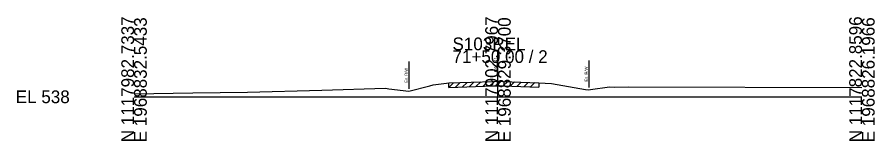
# Model space of a CAD drawing. Extents: x -26 to 163, y -10 to 24518.
# Drawn here: x -25.7 to 162.8, y 19990.3 to 20017.5 of the extents above; entities that cross this region are included whole.
import ezdxf

# ---------------------------------------------------------------- set-up
doc = ezdxf.new("R2010")
doc.units = 0
for name, color, linetype in [('RD_GPK_XS_Cell', 7, 'Continuous'), ('RD_XS_ExGround', 7, 'Continuous'), ('RD_XS_ExPaveRet', 7, 'Continuous'), ('RD_XS_ExRW', 7, 'Continuous'), ('RD_XS_TX_Elev_EX', 7, 'Continuous')]:
    doc.layers.add(name, color=color, linetype=linetype)

msp = doc.modelspace()

# ---------------------------------------------------------------- linework, layer by layer
at = {"layer": 'RD_GPK_XS_Cell'}
for p, q in [((80, 20000), (80, 20010.24)), ((0, 20000), (80, 20000)), ((80, 20000), (160, 20000))]:
    msp.add_line(p, q, dxfattribs=at)
at = {"layer": 'RD_XS_ExGround'}
msp.add_lwpolyline([(0, 20000.67), (12.96, 20000.89), (24.91, 20001.02), (41.3, 20001.48), (55.24, 20001.88), (56.02, 20001.77), (60.41, 20001.23), (65, 20002.41), (65.75, 20002.6), (68.67, 20002.98), (69.16, 20003.04), (79.02, 20003.38), (80.14, 20003.41), (81.04, 20003.38), (89.01, 20003.09), (91.77, 20002.96), (99.26, 20001.64), (99.96, 20001.52), (100.32, 20001.57), (104.53, 20002.17), (105.63, 20002.12), (108.59, 20002.18), (160, 20002.01)], dxfattribs=at)
at = {"layer": 'RD_XS_ExPaveRet'}
for p, q in [((76.66, 20002.3), (77.7, 20003.33)), ((78.16, 20002.35), (79.2, 20003.38)), ((79.66, 20002.4), (80.66, 20003.4)), ((81.16, 20002.38), (82.13, 20003.34)), ((69.16, 20002.04), (70.2, 20003.08)), ((69.16, 20002.04), (69.16, 20003.04)), ((69.16, 20002.04), (79.02, 20002.38)), ((70.66, 20002.09), (71.7, 20003.13)), ((72.16, 20002.15), (73.2, 20003.18)), ((73.66, 20002.2), (74.7, 20003.23)), ((75.16, 20002.25), (76.2, 20003.28)), ((79.02, 20002.38), (80.14, 20002.41)), ((80.14, 20002.41), (81.04, 20002.38)), ((81.04, 20002.38), (89.01, 20002.09)), ((82.66, 20002.32), (83.63, 20003.29)), ((84.16, 20002.27), (85.13, 20003.23)), ((85.66, 20002.21), (86.63, 20003.18)), ((87.16, 20002.16), (88.13, 20003.12)), ((89.01, 20003.09), (89.01, 20002.09))]:
    msp.add_line(p, q, dxfattribs=at)
at = {"layer": 'RD_XS_ExRW'}
for p, q in [((60.41, 20007.73), (60.41, 20001.73)), ((99.96, 20008.02), (99.96, 20002.02))]:
    msp.add_line(p, q, dxfattribs=at)

# ---------------------------------------------------------------- texts
at = {"layer": 'RD_GPK_XS_Cell'}
for s, p in [('N 1117982.7337', (0, 19990)), ('E 1968832.5433', (2.8, 19990)), ('N 1117902.7967', (80, 19990)), ('E 1968829.3700', (82.8, 19990)), ('N 1117822.8596', (160, 19990)), ('E 1968826.1966', (162.8, 19990))]:
    msp.add_text(s, height=2.8, rotation=90, dxfattribs=at).set_placement(p)
for s, p in [('S103REL', (70, 20010.24)), ('71+50.00 / 2', (70, 20007.44)), ('EL 538', (-26, 19998.6))]:
    msp.add_text(s, height=2.8, dxfattribs=at).set_placement(p)
at = {"layer": 'RD_XS_ExRW'}
for p in [(60.16, 20003.08), (99.71, 20003.36)]:
    msp.add_text('Ex. R/W ', height=0.65, rotation=90, dxfattribs=at).set_placement(p)
at = {"layer": 'RD_XS_TX_Elev_EX'}
msp.add_text('541.41', height=0.8, rotation=90, dxfattribs=at).set_placement((79.9, 20005.41))

doc.saveas('drawing.dxf')
